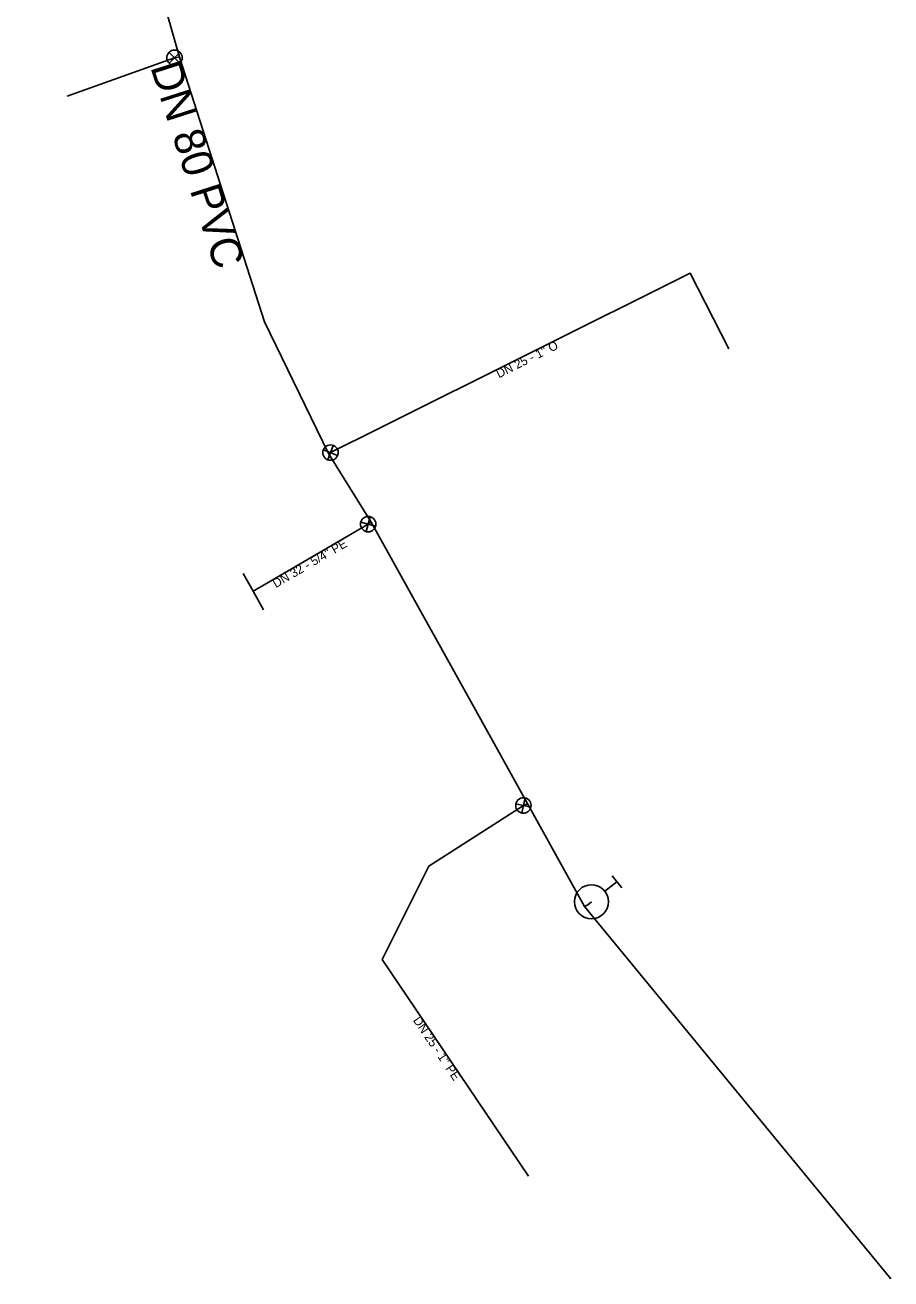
# Model space of a CAD drawing. Extents: x -446989 to -446811, y -1113341 to -1113211.
# Drawn here: x -446945.5 to -446900.7, y -1113340.6 to -1113275.8 of the extents above; entities that cross this region are included whole.
import ezdxf

# ---------------------------------------------------------------- set-up
doc = ezdxf.new("R2010")
doc.units = 0
for name, color, linetype in [('_hydrantova_odbocka_', 7, 'Continuous'), ('_pripojka_prevzato_z_dokumentace_', 7, 'Continuous'), ('_pripojka_priblizne_', 7, 'Continuous'), ('_voda_smvak_prevzato_z_dokumentace_', 7, 'Continuous'), ('Default', 7, 'Continuous'), ('MoLevel 28', 7, 'Continuous'), ('MoLevel 32', 7, 'Continuous'), ('MoLevel 46', 7, 'Continuous'), ('MoLevel 53', 7, 'Continuous')]:
    doc.layers.add(name, color=color, linetype=linetype)

# ---------------------------------------------------------------- blocks, each defined once
blk = doc.blocks.new('_uzaver_pripojka_')
at = {"layer": 'Default'}
for p, q in [((-0.000035, -0.000035), (0.000035, 0.000035)), ((0.000035, -0.000035), (-0.000035, 0.000035))]:
    blk.add_line(p, q, dxfattribs=at)
for radius in [0.00005, 0.0000025]:
    blk.add_circle((0, 0), radius, dxfattribs=at)
blk = doc.blocks.new('_hydrant_voda_')
at = {"layer": 'Default'}
for p, q in [((-0.0000225, 0.000095), (0.0000225, 0.000095)), ((0, 0.000095), (0, 0.00005))]:
    blk.add_line(p, q, dxfattribs=at)
blk.add_circle((0, 0), 0.00005, dxfattribs=at)

msp = doc.modelspace()

# ---------------------------------------------------------------- linework, layer by layer
at = {"layer": '_hydrantova_odbocka_'}
msp.add_lwpolyline([(-446916.53, -1113321.38), (-446916.35, -1113321.3), (-446916.17, -1113321.14)], dxfattribs=at)
at = {"layer": '_pripojka_prevzato_z_dokumentace_'}
msp.add_lwpolyline([(-446937.48, -1113277.45), (-446937.74, -1113277.49), (-446943.294, -1113279.479)], dxfattribs=at)
at = {"layer": '_pripojka_priblizne_'}
for p, q in [((-446933.668, -1113305.08), (-446934.188, -1113304.167)), ((-446933.095, -1113304.745), (-446933.668, -1113305.08)), ((-446933.668, -1113305.08), (-446933.132, -1113306.045))]:
    msp.add_line(p, q, dxfattribs=at)
for points in [[(-446927.272, -1113296.713), (-446911.067, -1113288.622), (-446909.056, -1113292.538)], [(-446929.78, -1113297.96), (-446929.67, -1113297.91), (-446927.272, -1113296.713)], [(-446927.56, -1113301.51), (-446927.72, -1113301.61), (-446933.095, -1113304.745)], [(-446919.483, -1113316.073), (-446919.69, -1113316.16), (-446924.582, -1113319.3)], [(-446924.582, -1113319.3), (-446926.996, -1113324.122), (-446919.434, -1113335.335)]]:
    msp.add_lwpolyline(points, dxfattribs=at)
at = {"layer": '_voda_smvak_prevzato_z_dokumentace_'}
msp.add_line((-446900.678, -1113340.649), (-446916.53, -1113321.38), dxfattribs=at)
msp.add_lwpolyline([(-446916.53, -1113321.38), (-446919.448, -1113316.136), (-446921.211, -1113312.955), (-446927.56, -1113301.51), (-446929.78, -1113297.96), (-446933.08, -1113291.15), (-446937.48, -1113277.45), (-446943.5, -1113256.4), (-446945.47, -1113246.96)], dxfattribs=at)

# ---------------------------------------------------------------- block references
at = {"layer": 'MoLevel 28', "xscale": 17636.68430335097, "yscale": 17636.684303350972, "rotation": -51.96585347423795}
msp.add_blockref('_hydrant_voda_', (-446916.17, -1113321.14), dxfattribs=at)
at = {"layer": 'MoLevel 53', "xscale": 7999.999999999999, "yscale": 7999.999999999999}
msp.add_blockref('_uzaver_pripojka_', (-446937.74, -1113277.49), dxfattribs=at)
at = {"layer": 'MoLevel 53'}
for p, xscale, yscale, rotation in [((-446929.67, -1113297.91), 7999.999999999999, 7999.999999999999, 23.317708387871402), ((-446927.72, -1113301.61), 7999.999999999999, 8000, -149.7423031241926), ((-446919.69, -1113316.16), 7999.999999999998, 8000, -147.30129577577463)]:
    msp.add_blockref('_uzaver_pripojka_', p, dxfattribs=dict(at, xscale=xscale, yscale=yscale, rotation=rotation))

# ---------------------------------------------------------------- texts
at = {"layer": 'MoLevel 32'}
for s, rotation, p in [("DN 25 - 1'' O", 26.53178, (-446920.957, -1113294.069)), ("DN 32 - 5/4'' PE", 30.2577, (-446932.496, -1113304.923)), ("DN 25 - 1'' PE", 303.99557, (-446925.42, -1113327.272))]:
    msp.add_text(s, height=0.455, rotation=rotation, dxfattribs=at).set_placement(p)
at = {"layer": 'MoLevel 46'}
msp.add_text('DN 80 PVC', height=1.6049, rotation=287.80535, dxfattribs=at).set_placement((-446939, -1113277.965))

doc.saveas('drawing.dxf')
